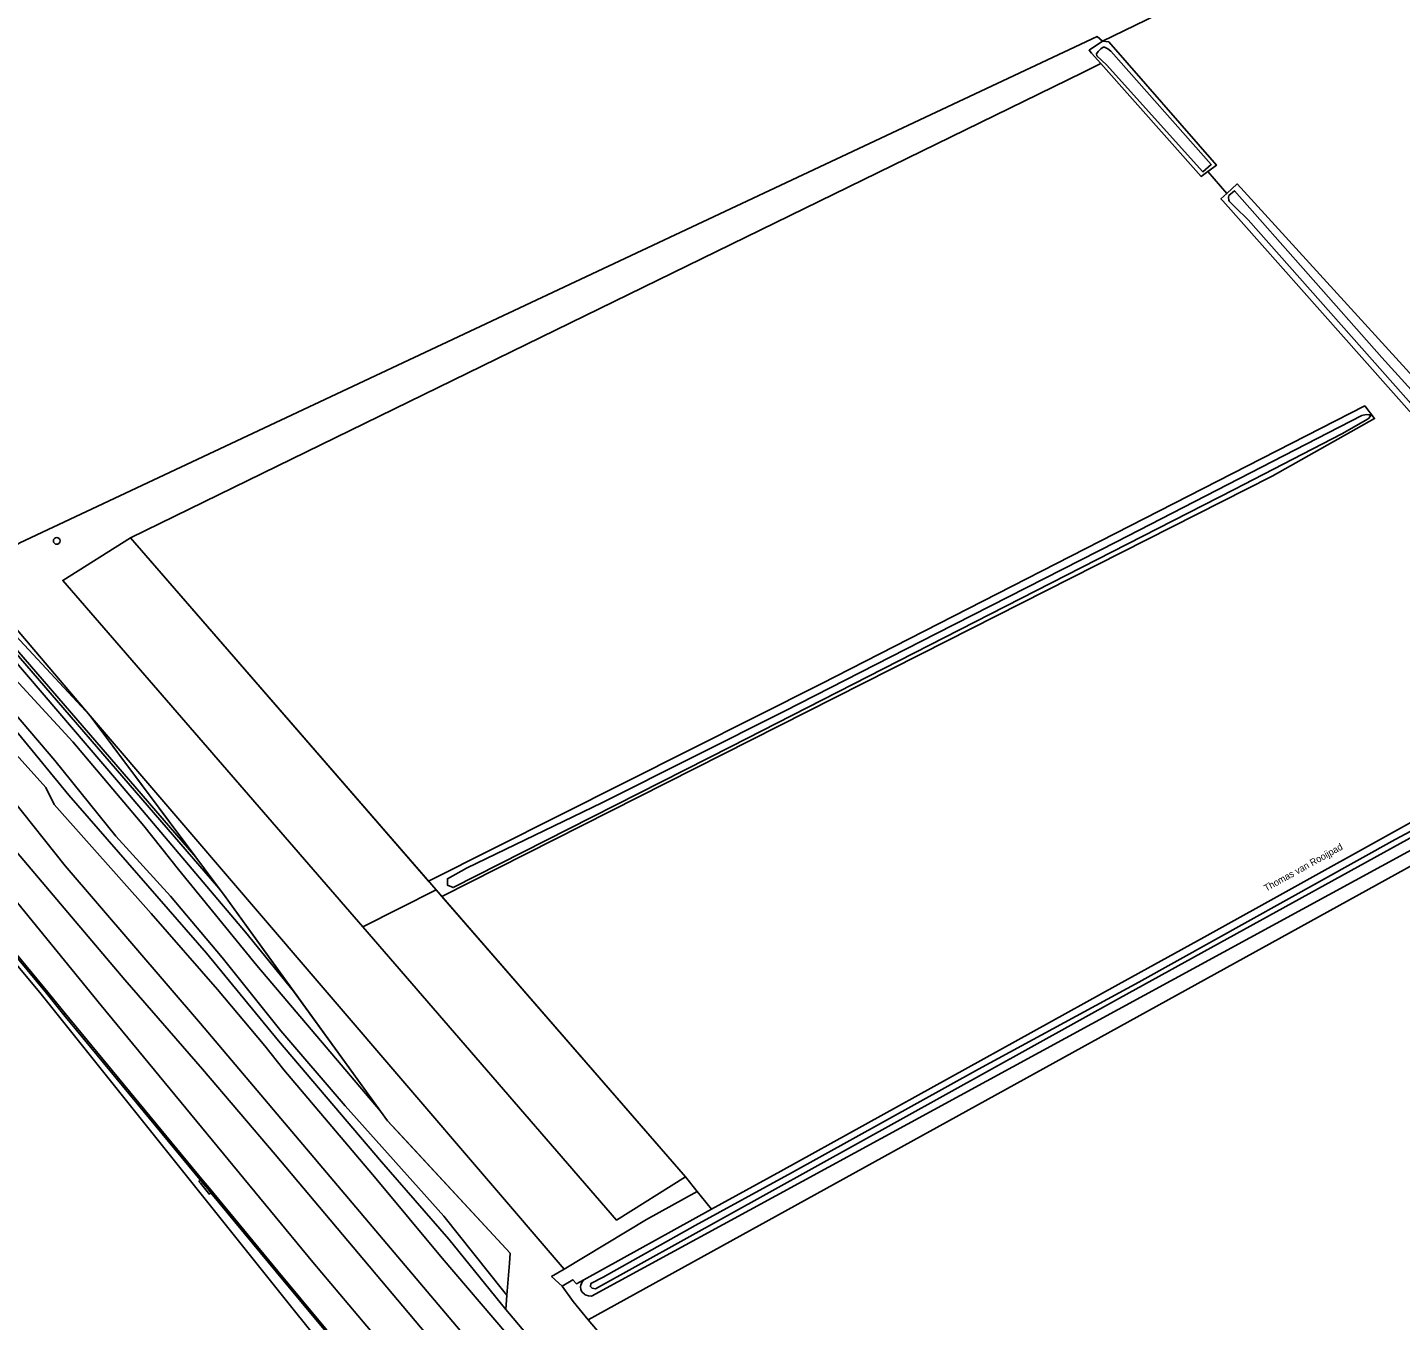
# Model space of a CAD drawing. Extents: x 164494 to 166241, y 382475 to 384495.
# Drawn here: x 165148.9 to 165350.9, y 382608.2 to 382798.6 of the extents above; entities that cross this region are included whole.
import ezdxf

# ---------------------------------------------------------------- set-up
doc = ezdxf.new("R2010")
doc.units = 0
for name, color, linetype in [('IMGEO_Boom', 7, 'Continuous'), ('IMGEO_Geluidsscherm', 7, 'Continuous'), ('IMGEO_Grasland_agrarisch', 7, 'Continuous'), ('IMGEO_Grasland_overig', 7, 'Continuous'), ('IMGEO_Groenvoorziening', 7, 'Continuous'), ('IMGEO_Hek', 7, 'Continuous'), ('IMGEO_Loofbos', 7, 'Continuous'), ('IMGEO_Muur', 7, 'Continuous'), ('IMGEO_Oever', 7, 'Continuous'), ('IMGEO_Openbare_ruimte_label', 7, 'Continuous'), ('IMGEO_Spoor', 7, 'Continuous'), ('IMGEO_Spoorbaan_halfverhard', 7, 'Continuous'), ('IMGEO_Struiken', 7, 'Continuous'), ('IMGEO_Terreindeel_gesloten', 7, 'Continuous'), ('IMGEO_Waterloop', 7, 'Continuous')]:
    doc.layers.add(name, color=color, linetype=linetype)

msp = doc.modelspace()

# ---------------------------------------------------------------- linework, layer by layer
at = {"layer": 'IMGEO_Boom'}
msp.add_circle((165153.16, 382723.01), 0.489, dxfattribs=at)
at = {"layer": 'IMGEO_Geluidsscherm'}
for points in [[(165141.43, 382668.74), (165151.66, 382656.42), (165154.22, 382653.27)], [(165141.63, 382668.9), (165151.85, 382656.58), (165154.41, 382653.42)], [(165154.22, 382653.27), (165174.53, 382628.66), (165175.39, 382627.62), (165185.52, 382615.35), (165216.95, 382577.51), (165222.04, 382571.33), (165227.23, 382564.93), (165228.07, 382565.63)], [(165154.41, 382653.42), (165174.72, 382628.82), (165175.58, 382627.78), (165185.71, 382615.51), (165217.14, 382577.67), (165222.23, 382571.49), (165227.07, 382565.52), (165227.12, 382565.46)]]:
    msp.add_lwpolyline(points, dxfattribs=at)
at = {"layer": 'IMGEO_Grasland_agrarisch'}
msp.add_lwpolyline([(165147.73, 382722.73), (165306.26, 382797.27), (165307.05, 382796.58), (165307.99, 382796.47), (165323.83, 382778.32), (165323.43, 382778.03), (165322.55, 382777.38), (165325.35, 382774.18), (165326.88, 382775.58), (165389.84, 382706.54)], dxfattribs=at)
for points in [[(165345.24, 382750), (165324.77, 382773.07), (165324.49, 382773.39), (165325.35, 382774.18), (165322.55, 382777.38), (165321.58, 382776.67), (165306.81, 382793.31), (165306.03, 382792.88), (165304.18, 382791.97), (165164.03, 382723.48), (165207.89, 382672.93), (165265.64, 382701.97), (165345.65, 382742.9), (165347.1, 382741.03), (165332.05, 382732.53), (165280.34, 382706.35), (165280.13, 382706.24), (165209.86, 382670.66), (165245.68, 382629.39), (165247.42, 382627.24), (165248.7, 382625.67), (165249.54, 382624.64), (165259.71, 382630.25), (165309.39, 382657.69), (165322.04, 382664.7), (165388.32, 382701.46)], [(165425.5, 382538.24), (165418.91, 382549.58), (165416.19, 382554.47), (165400.96, 382584.41), (165388.9, 382607.3), (165379.91, 382625.45), (165374.99, 382635.66), (165355.79, 382676.99), (165231.39, 382608.37), (165248.77, 382587.82), (165257.29, 382578.44), (165262.78, 382578.65), (165266.56, 382578.95), (165266.59, 382574.97), (165262.47, 382574.93), (165261.94, 382573.12), (165270.16, 382563.93), (165272.43, 382562.04), (165323.58, 382553.4), (165367.77, 382546.66)]]:
    msp.add_lwpolyline(points, close=True, dxfattribs=at)
at = {"layer": 'IMGEO_Grasland_overig'}
for points in [[(165139.25, 382700.34), (165151.56, 382686.73), (165152.78, 382684.22), (165167.08, 382668.17), (165176.83, 382656.96), (165183.81, 382648.67), (165186.58, 382645.14), (165200.19, 382629.1), (165209.89, 382617.44), (165219.35, 382606.34), (165230.31, 382593.23), (165239.17, 382583.35), (165252.45, 382569.64), (165252.19, 382570.91), (165219.26, 382609.88), (165210.87, 382620.22), (165200.98, 382631.61), (165185.78, 382649.4), (165175.22, 382662.33), (165154.96, 382685.6), (165144.53, 382698.21)], [(165219.35, 382606.34), (165209.89, 382617.44), (165200.19, 382629.1), (165186.58, 382645.14), (165183.81, 382648.67), (165176.83, 382656.96), (165167.08, 382668.17), (165152.78, 382684.22), (165151.56, 382686.73), (165139.25, 382700.34)], [(165146.61, 382685.01), (165154.41, 382675.2), (165174.33, 382651.99), (165201.75, 382619.52), (165221.69, 382595.91)], [(165359.77, 382681.45), (165231.84, 382611.82), (165231.44, 382611.88), (165231.07, 382611.98), (165230.95, 382612.04), (165230.81, 382612.11), (165230.46, 382612.49), (165230.31, 382612.83), (165230.25, 382613.22), (165230.27, 382613.43), (165230.5, 382613.93), (165230.74, 382614.26), (165229.66, 382613.66), (165229.14, 382614.26), (165227.54, 382613.3), (165229.16, 382611.05), (165231.39, 382608.37), (165355.79, 382676.99)]]:
    msp.add_lwpolyline(points, dxfattribs=at)
msp.add_lwpolyline([(165249.54, 382624.64), (165248.7, 382625.67), (165247.42, 382627.24), (165239.96, 382623.12), (165227.82, 382615.8), (165226, 382614.71), (165227.54, 382613.3), (165229.14, 382614.26), (165229.66, 382613.66), (165230.74, 382614.26)], close=True, dxfattribs=at)
at = {"layer": 'IMGEO_Groenvoorziening'}
for points in [[(165050.46, 382776.61), (165150.68, 382656.53), (165227.26, 382560.78), (165232.98, 382559.76), (165228.61, 382564.98), (165228.07, 382565.63), (165227.23, 382564.93), (165222.04, 382571.33), (165216.95, 382577.51), (165185.52, 382615.35), (165175.85, 382627.06), (165175.62, 382626.87), (165175.51, 382627.01), (165174.3, 382628.47), (165174.09, 382628.72), (165174.32, 382628.91), (165154.22, 382653.27), (165151.66, 382656.42), (165141.43, 382668.74)], [(165248.77, 382587.82), (165231.39, 382608.37), (165229.16, 382611.05), (165227.54, 382613.3), (165226, 382614.71), (165227.82, 382615.8), (165158.11, 382697.26), (165173.63, 382676.45), (165177.02, 382671.91), (165177.7, 382671), (165188.03, 382656.73), (165200.81, 382639.08), (165201.86, 382637.62), (165203.99, 382635.33), (165219.91, 382618.16), (165219.79, 382616.68), (165219.42, 382611.97), (165219.26, 382609.88), (165252.19, 382570.91)]]:
    msp.add_lwpolyline(points, dxfattribs=at)
at = {"layer": 'IMGEO_Hek'}
for points in [[(165307.05, 382796.58), (165395, 382839.26)], [(165198.2, 382666.19), (165154.04, 382717.2), (165164.03, 382723.48), (165209, 382671.65)], [(165140.36, 382718.08), (165158.11, 382697.26), (165174.9, 382674.75), (165177.7, 382671), (165201.86, 382637.62), (165219.91, 382618.16), (165219.79, 382616.68), (165219.42, 382611.97), (165219.26, 382609.88), (165252.19, 382570.91), (165254.3, 382568.42), (165248.76, 382563.58)], [(165231.39, 382608.37), (165355.79, 382676.99), (165374.99, 382635.66), (165379.91, 382625.45), (165388.9, 382607.3), (165400.96, 382584.41)], [(165209, 382671.65), (165245.68, 382629.39), (165235.56, 382623.03)], [(165235.56, 382623.03), (165198.2, 382666.19)]]:
    msp.add_lwpolyline(points, dxfattribs=at)
at = {"layer": 'IMGEO_Loofbos'}
for points in [[(165304.18, 382791.97), (165306.03, 382792.88), (165306.81, 382793.31), (165305.45, 382794.84), (165305.1, 382795.25), (165307.05, 382796.58), (165306.26, 382797.27), (165147.73, 382722.73), (165139.3, 382717.42), (165158.11, 382697.26), (165227.82, 382615.8), (165239.96, 382623.12), (165247.42, 382627.24), (165245.68, 382629.39), (165235.56, 382623.03), (165198.2, 382666.19), (165154.04, 382717.2), (165164.03, 382723.48)], [(165164.03, 382723.48), (165154.04, 382717.2), (165198.2, 382666.19), (165209, 382671.65), (165207.89, 382672.93)], [(165209.86, 382670.66), (165209, 382671.65), (165198.2, 382666.19), (165235.56, 382623.03), (165245.68, 382629.39)]]:
    msp.add_lwpolyline(points, close=True, dxfattribs=at)
at = {"layer": 'IMGEO_Muur'}
msp.add_lwpolyline([(165141.43, 382668.74), (165151.66, 382656.42), (165154.22, 382653.27), (165154.41, 382653.42), (165151.85, 382656.58), (165141.63, 382668.9)], dxfattribs=at)
msp.add_lwpolyline([(165185.52, 382615.35), (165216.95, 382577.51), (165222.04, 382571.33), (165227.23, 382564.93), (165228.07, 382565.63), (165227.94, 382565.79), (165227.71, 382566.05), (165227.07, 382565.52), (165222.23, 382571.49), (165217.14, 382577.67), (165185.71, 382615.51), (165175.58, 382627.78), (165174.72, 382628.82), (165154.41, 382653.42), (165154.22, 382653.27), (165174.32, 382628.91), (165174.53, 382628.66), (165175.39, 382627.62), (165175.85, 382627.06)], close=True, dxfattribs=at)
at = {"layer": 'IMGEO_Oever'}
for points in [[(165028.15, 382845.7), (165027.12, 382844.95), (165031.29, 382840.23), (165043.46, 382826.05), (165061.34, 382804.88), (165070.04, 382795.12), (165083.17, 382779.94), (165086.92, 382776.02), (165096.77, 382765.03), (165105.02, 382754.95), (165119.18, 382738.24), (165138.17, 382716.84), (165138.56, 382717.02), (165173.63, 382676.45), (165158.11, 382697.26), (165139.3, 382717.42)], [(165307.05, 382796.58), (165305.1, 382795.25), (165305.45, 382794.84), (165306.81, 382793.31), (165321.58, 382776.67), (165322.55, 382777.38), (165323.43, 382778.03), (165323.83, 382778.32), (165307.99, 382796.47)], [(165323.06, 382778.45), (165321.83, 382777.35), (165307.63, 382793.08), (165306.21, 382794.44), (165306.19, 382794.71), (165306.41, 382795.06), (165306.82, 382795.44), (165307.14, 382795.68), (165307.37, 382795.68), (165307.83, 382795.46), (165308.3, 382795.13)], [(165280.13, 382706.24), (165280.34, 382706.35), (165332.05, 382732.53), (165347.1, 382741.03), (165345.65, 382742.9), (165265.64, 382701.97), (165207.89, 382672.93), (165209, 382671.65), (165209.86, 382670.66)], [(165260.26, 382697.93), (165282.62, 382709.37), (165309.1, 382722.9), (165345.24, 382741.47), (165345.87, 382741.61), (165346.28, 382741.57), (165346.42, 382741.56), (165346.51, 382741.39), (165346.18, 382740.99), (165342.3, 382738.78), (165326.46, 382730.57), (165252.44, 382692.77), (165211.51, 382671.99), (165210.67, 382672.35), (165210.67, 382673.27), (165213.45, 382674.84), (165233.49, 382684.53)], [(165173.63, 382676.45), (165138.56, 382717.02), (165138.17, 382716.84), (165177.02, 382671.91)], [(165188.03, 382656.73), (165180.95, 382665.44), (165162.24, 382687.51), (165137.45, 382716.5), (165135.14, 382715.41), (165137.37, 382712.64), (165145.33, 382704.55), (165155.54, 382693.42), (165165.99, 382681.07), (165171.09, 382674.64), (165182.61, 382660.53), (165200.81, 382639.08)]]:
    msp.add_lwpolyline(points, close=True, dxfattribs=at)
for points in [[(165389.84, 382706.54), (165326.88, 382775.58), (165325.35, 382774.18), (165324.49, 382773.39), (165324.77, 382773.07), (165345.24, 382750), (165388.32, 382701.46), (165322.04, 382664.7), (165309.39, 382657.69), (165259.71, 382630.25), (165249.54, 382624.64), (165230.74, 382614.26), (165230.5, 382613.93), (165230.27, 382613.43), (165230.25, 382613.22), (165230.31, 382612.83), (165230.46, 382612.49), (165230.81, 382612.11), (165230.95, 382612.04), (165231.07, 382611.98), (165231.44, 382611.88), (165231.84, 382611.82), (165359.77, 382681.45)], [(165354.34, 382741.08), (165328.5, 382770.3), (165326.61, 382772.16), (165326.1, 382772.65), (165325.89, 382772.85), (165325.72, 382773.05), (165325.65, 382773.18), (165325.61, 382773.55), (165325.64, 382773.84), (165326.48, 382774.57), (165348.17, 382750), (165388.54, 382705.53)], [(165358.08, 382682.43), (165309.58, 382655.69), (165232.47, 382612.89), (165231.96, 382613), (165231.71, 382613.25), (165231.77, 382613.71), (165233.56, 382614.64), (165247.12, 382622.24), (165261.32, 382630), (165288.82, 382645.23), (165312.39, 382658.04), (165350.14, 382679.06), (165369.12, 382689.16)]]:
    msp.add_lwpolyline(points, dxfattribs=at)
at = {"layer": 'IMGEO_Spoor'}
for points in [[(164971.84, 382886.62), (165028.93, 382818.52), (165059.9, 382781.2), (165071.68, 382767.17), (165111.26, 382719.76), (165163.2, 382658.4), (165174.6, 382645.25), (165185.3, 382632.69), (165237.74, 382570.35), (165244.67, 382561.92)], [(164968.87, 382884.12), (165014.68, 382829.39), (165077.86, 382753.28), (165088.51, 382740.65), (165118.9, 382704.2), (165145.22, 382672.37), (165159.72, 382654.6), (165190.85, 382616.84), (165202.75, 382602.69), (165235.6, 382563.21)]]:
    msp.add_lwpolyline(points, dxfattribs=at)
at = {"layer": 'IMGEO_Spoorbaan_halfverhard'}
for points in [[(165221.69, 382595.91), (165201.75, 382619.52), (165174.33, 382651.99), (165154.41, 382675.2), (165146.61, 382685.01)], [(165141.63, 382668.9), (165151.85, 382656.58), (165154.41, 382653.42), (165174.72, 382628.82), (165175.58, 382627.78), (165185.71, 382615.51), (165217.14, 382577.67)]]:
    msp.add_lwpolyline(points, dxfattribs=at)
at = {"layer": 'IMGEO_Struiken'}
for points in [[(165143.23, 382701.96), (165152.9, 382690.69), (165161.86, 382679.57), (165169.92, 382670.73), (165177.49, 382661.69), (165186.13, 382650.91), (165195.62, 382639.86), (165210.13, 382623.63), (165218.96, 382612.53), (165219.42, 382611.97), (165219.79, 382616.68), (165219.91, 382618.16), (165203.99, 382635.33), (165201.86, 382637.62), (165200.81, 382639.08), (165182.61, 382660.53), (165171.09, 382674.64), (165165.99, 382681.07), (165155.54, 382693.42), (165145.33, 382704.55)], [(165144.53, 382698.21), (165154.96, 382685.6), (165175.22, 382662.33), (165185.78, 382649.4), (165200.98, 382631.61), (165210.87, 382620.22), (165219.26, 382609.88), (165219.42, 382611.97), (165218.96, 382612.53), (165210.13, 382623.63), (165195.62, 382639.86), (165186.13, 382650.91), (165177.49, 382661.69), (165169.92, 382670.73), (165161.86, 382679.57), (165152.9, 382690.69), (165143.23, 382701.96)]]:
    msp.add_lwpolyline(points, dxfattribs=at)
at = {"layer": 'IMGEO_Terreindeel_gesloten'}
msp.add_lwpolyline([(165175.39, 382627.62), (165174.53, 382628.66), (165174.32, 382628.91), (165174.09, 382628.72), (165174.3, 382628.47), (165175.51, 382627.01), (165175.62, 382626.87), (165175.85, 382627.06)], close=True, dxfattribs=at)
at = {"layer": 'IMGEO_Waterloop'}
for points in [[(165308.3, 382795.13), (165307.83, 382795.46), (165307.37, 382795.68), (165307.14, 382795.68), (165306.82, 382795.44), (165306.41, 382795.06), (165306.19, 382794.71), (165306.21, 382794.44), (165307.63, 382793.08), (165321.83, 382777.35), (165323.06, 382778.45)], [(165260.26, 382697.93), (165233.49, 382684.53), (165213.45, 382674.84), (165210.67, 382673.27), (165210.67, 382672.35), (165211.51, 382671.99), (165252.44, 382692.77), (165326.46, 382730.57), (165342.3, 382738.78), (165346.18, 382740.99), (165346.51, 382741.39), (165346.42, 382741.56), (165346.28, 382741.57), (165345.87, 382741.61), (165345.24, 382741.47), (165309.1, 382722.9), (165282.62, 382709.37)], [(165177.02, 382671.91), (165138.17, 382716.84), (165137.45, 382716.5), (165162.24, 382687.51), (165180.95, 382665.44), (165188.03, 382656.73), (165177.7, 382671)]]:
    msp.add_lwpolyline(points, close=True, dxfattribs=at)
for points in [[(165388.54, 382705.53), (165348.17, 382750), (165326.48, 382774.57), (165325.64, 382773.84), (165325.61, 382773.55), (165325.65, 382773.18), (165325.72, 382773.05), (165325.89, 382772.85), (165326.1, 382772.65), (165326.61, 382772.16), (165328.5, 382770.3), (165354.34, 382741.08)], [(165369.12, 382689.16), (165350.14, 382679.06), (165312.39, 382658.04), (165288.82, 382645.23), (165261.32, 382630), (165247.12, 382622.24), (165233.56, 382614.64), (165231.77, 382613.71), (165231.71, 382613.25), (165231.96, 382613), (165232.47, 382612.89), (165309.58, 382655.69), (165358.08, 382682.43)]]:
    msp.add_lwpolyline(points, dxfattribs=at)

# ---------------------------------------------------------------- texts
at = {"layer": 'IMGEO_Openbare_ruimte_label'}
msp.add_text('Thomas van Rooijpad', height=1, rotation=29.0268, dxfattribs=at).set_placement((165331.16, 382671.37))

doc.saveas('drawing.dxf')
